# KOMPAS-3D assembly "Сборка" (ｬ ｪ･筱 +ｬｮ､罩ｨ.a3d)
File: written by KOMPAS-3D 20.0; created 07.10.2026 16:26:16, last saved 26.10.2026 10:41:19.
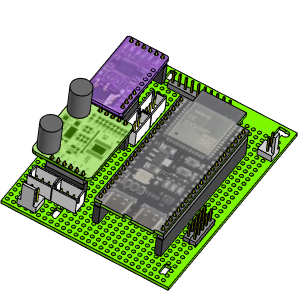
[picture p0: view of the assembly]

Document properties: Полное имя файла: D:\RicWork\Project-EPS32\box_compas\сборки компонентов\макетка+модули.a3d

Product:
- Part/product: Сборка
    Масса: 0.132179
  - Component [detail]: Деталь  | Масса: 0.00130352; source file: ..\разъемы\pls_10.m3d
  - Component [detail]: Деталь  | Масса: 0.000929543; source file: ..\разъемы\WF-2 (DS1070-2 M).m3d
  - Component [detail]: Деталь  | qty 4  | Масса: 0.00117184; source file: ..\разъемы\B3B-XH-A.m3d
  - Component [assembly]: Сборка  | Масса: 0.0226054; source file: ..\усилитель\HT8698_asm+.a3d
  - Component [detail]: Деталь  | Масса: 0.050617; source file: ..\макетки\Макетная плата_01.m3d
  - Component [detail]: Деталь  | qty 2  | Масса: 0.000651758; source file: ..\разъемы\pls_5.m3d
  - Component [assembly]: Сборка  | Масса: 0.0106182; source file: ..\цап ацп\pcm5102A_asm+.a3d
  - Component [detail]: Деталь  | Масса: 0.00147109; source file: ..\разъемы\WF-3 (DS1070-3 M).m3d
  - Component [assembly]: Сборка  | Масса: 0.0386432; source file: ..\esp32\esp32-s3-n16r8_asm+.a3d

Referenced files in D:\RicWork\Project-EPS32\box_compas\макетки\: Макетная плата_01.m3d
Referenced files in D:\RicWork\Project-EPS32\box_compas\разъемы\: pls_5.m3d, B3B-XH-A.m3d, WF-3 (DS1070-3 M).m3d, WF-2 (DS1070-2 M).m3d, pls_10.m3d
Referenced files in D:\RicWork\Project-EPS32\box_compas\усилитель\: HT8698_asm+.a3d
Referenced files in D:\RicWork\Project-EPS32\box_compas\цап ацп\: pcm5102A_asm+.a3d
Referenced files in D:\RicWork\Project-EPS32\box_compas\esp32\: esp32-s3-n16r8_asm+.a3d
Referenced files in D:\myProjects\Progect_esp32\box_compas\разъемы\: B3B-XH-A.m3d, WF-3 (DS1070-3 M).m3d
